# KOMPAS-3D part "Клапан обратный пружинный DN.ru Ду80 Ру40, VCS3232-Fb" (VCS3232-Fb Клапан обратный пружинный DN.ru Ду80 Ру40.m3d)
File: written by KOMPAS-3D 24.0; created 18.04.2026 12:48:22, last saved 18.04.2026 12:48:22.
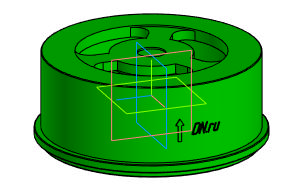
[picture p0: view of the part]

Document properties: Автор: 712; Полное имя файла: C:\Users\712\Desktop\Новая папка (4)\VCS3232-Fb Клапан обратный пружинный DN.ru Ду80 Ру40.m3d

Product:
- Component: Пружина 1086-1017 ГОСТ 18793-80  | qty 1  | additional columns: 3953604318-4147491677-0; Деталь; Пользователь Windows; c; Шероховатость не задана; Да; Сталь 10  ГОСТ 1050-88; source file: Деталь_6.m3d
- Body: Тело 1  | qty 1
    Масса: 2.746242
- Part/product: Клапан обратный пружинный DN.ru Ду80 Ру40  | designation VCS3232-Fb
    Масса: 2.1
    Раздел спецификации: Прочие изделия
    Примечание: D100-03906
    additional columns: 071bd168-1a06-425c-849c-e99e84a96128; Деталь; 712; c; Шероховатость не задана; Да

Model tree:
1. Операция без истории:2

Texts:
  VCS3232-Fb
